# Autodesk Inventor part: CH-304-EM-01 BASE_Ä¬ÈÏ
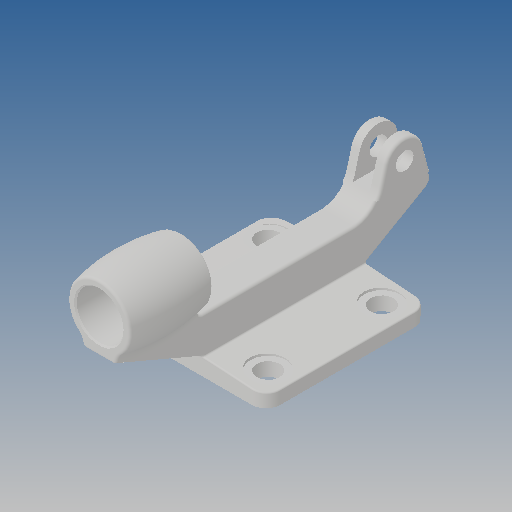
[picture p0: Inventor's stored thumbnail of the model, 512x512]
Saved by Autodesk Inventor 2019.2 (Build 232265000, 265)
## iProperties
Created: 2010-06
Part Number: CH-304-EM-01 BASE_Ä¬ÈÏ
Material: Ogólny
Document SubType Name: Modeling
Designer: CADENGINEERING4
Density: 1 g/cm^3
Appearance: Domyślna
Author: CADENGINEERING4
Revision Number: ÈÎºÎ
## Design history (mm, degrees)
feature "NONE"
node "Bryła1"
